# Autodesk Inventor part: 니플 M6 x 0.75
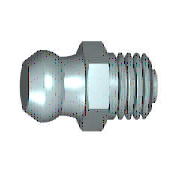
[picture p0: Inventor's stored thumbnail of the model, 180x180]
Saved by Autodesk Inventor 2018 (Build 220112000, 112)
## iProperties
IsCustomPart: 1
Created: 2012-02
Part Number: 니플 M6 x 0.75
Material: 강철, 연강
Description: 윤활 니플, 원추 유형 A
Document SubType Name: Modeling
Standard: JIS B 1575
Designer: mduedu
Standards Organization: JIS
Language: ko-KR
Size Designation: MT 6 x 0.75
Categories: <MemberInstance><Categories><Category DisplayName="기타 부품" InternalName="5aa15e00-363f-49f2-933f-16f664388e3f" Mnemonic="OTHER"><Category DisplayName="그리스 부속품" I
Density: 7.86 g/cm^3
Mass: 3.2546 g
Surface Area: 3.29319 cm^2
Volume: 0.414071 cm^3
Appearance: 금색
Author: mduedu
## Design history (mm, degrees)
sketch "스케치1"
  geometry: L1 (-8.8, 0)-(-8.8, 2.4); L2 (-8.8, 2.4)-(-7.335, 3.202); L3 (-8.8, 0)-(4.7, 0); L4 (4.7, 0)-(4.7, 1.5); L5 (4.7, 1.5)-(4, 1.5); L6 (4, 1.5)-(4, 3); L7 (4, 3)-(0, 3); L8 (-11.5, 0)-(7.4, 0) reference; L9 (0, -1.733)-(0, 10.398) reference; L10 (-3, 3.5)-(0, 3.5); L11 (0, 3.5)-(0, 3); A1 r 3.3 centre (-6.535, 0) between (-4.789, 2.8) and (-7.335, 3.202); A2 r 6 centre (-6.053, 8.665) between (-4.789, 2.8) and (-3, 3.5)
  constraints: 18 end point, 5 perpendicular, 4 point on circle, 2 centre point, 2 parallel, 2 point on line, 1 collinear, 1 vertical
  dimensions: "d0" = 13.5 distance between parallel lines of L1 L4 (= GL); "d1" = 5.6 diameter of A1.start L3 (= KGB2); "d2" = 0.7 distance between parallel lines of L4 L6 (= PHH); "d3" = 3 diameter of L5 L3 (= 0.5 x NND); "d4" = 6 diameter of L7 L3 (= NND); "d5" = 6.6 dimension on A1 L3 (= KR); "d6" = 4.8 diameter of L1.end L3 (= KGB1); "d7" = 6 radius of A2 (= RBN); "d11" = 7 diameter of L10.start L3 (= SW); "d14" = 3 distance of L10.start L10.end (= KOH); "d15" = 4 distance between parallel lines of L6 L11 (= NLG); "d61" = 7.33505 distance from line of L9 L2.end (computed from KGB1, KR, PHH, GL, NLG, VERS); "d62" = 6.53505 distance from line of L9 A1.centre (computed from NLG, GL, PHH, KR, KGB1)
revolve "본체" sketch "스케치1" stored, may be unused: angle "d25" = 90 deg
sketch "스케치2"
  geometry: L1 (2.021, 3.5)-(4.041, 0); L2 (4.041, 0)-(2.021, -3.5); L3 (2.021, -3.5)-(-2.021, -3.5); L4 (-2.021, -3.5)-(-4.041, 0); L5 (-4.041, 0)-(-2.021, 3.5); L6 (-2.021, 3.5)-(2.021, 3.5); C1 r 3.5 at (0, 0) reference; 1 further point
  constraints: 12 end point, 1 coincident, 1 horizontal, 1 tangent, 11 other
extrude "머리" join sketch "스케치2" distance "d17" = 3 (= KOH); taper "d18" = 0 deg
sketch "스케치3"
  geometry: L1 (2.687, 4.041)-(3, 4.041); L2 (3, 4.041)-(3, 3.5); L3 (3, 3.5)-(2.687, 4.041); L4 (0.313, 4.041)-(0, 4.041); L5 (0, 4.041)-(0, 3.5); L6 (0, 3.5)-(0.313, 4.041); L7 (3.6, 0)-(-0.6, 0) reference; L8 (0, 4.041)-(0, 2.021) reference; L9 (0, 4.041)-(3, 4.041) reference; L10 (3, 3.031)-(3, 4.041) reference
  constraints: 12 end point, 4 collinear, 3 perpendicular, 1 horizontal
  dimensions: "d19" = 3.5 distance from line of L5.end L7 (= 0.5 x SW); "d20" = 3.5 distance from line of L2.end L7 (= 0.5 x SW); "d21" = 30 deg angle of L6 L5; "d22" = 30 deg angle of L2 L3
revolve "모따기1" sketch "스케치3" stored, may be unused: angle "d56" = 90 deg
body "Solid1"
fillet "모깎기1" dims "d8" = 0.2 (= RR)
feature "스레드1" dims "d9" = 3.53991 (= NLG - GAL), "d10" = 0
chamfer "모따기2" distance "d23" = 0.46009 (= -0.5 x GD1 + 0.5 x NND); stored, may be unused: angle "d24" = 45 deg, second distance "d59" = 0.46009 (= -0.5 x GD1 + 0.5 x NND)
other parameters: "NLG" = 4 [user parameter; used in 4 equation terms], "GL" = 13.5 [user parameter; used in 3 equation terms], "NND" = 6 [user parameter; used in 4 equation terms], "KGB1" = 4.8 [user parameter; used in 3 equation terms], "KGB2" = 5.6 [user parameter; used in 1 equation term], "VERS" = 0.8 [user parameter; used in 1 equation term], "KR" = 6.6 [user parameter; used in 3 equation terms], "RBN" = 6 [user parameter; used in 1 equation term], "SW" = 7 [user parameter; used in 3 equation terms], "KOH" = 3 [user parameter; used in 2 equation terms], "GAL" = 0.46009 (= 0.61345 x PTC) [user parameter; used in 1 equation term], "FAWI" = 45 deg [user parameter], "PHH" = 0.7 [user parameter; used in 3 equation terms], "GD1" = 5.07983 (= THREADDIA - 1.2269 x PTC) [user parameter; used in 2 equation terms], "RR" = 0.2 [user parameter; used in 1 equation term], "d12" = 0, "d13" = 0, "GUL" = 0.46009 (= 0.61345 x PTC) [user parameter], "TPU" = 13.33333 (computed from PTC) [user parameter], "DULO" = 1.5 [user parameter], "PTC" = 0.75 [user parameter; used in 4 equation terms], "GEL" = 4 [user parameter], "THREADDIA" = 6 [user parameter; used in 1 equation term], "TOA" = 30 deg [user parameter]
